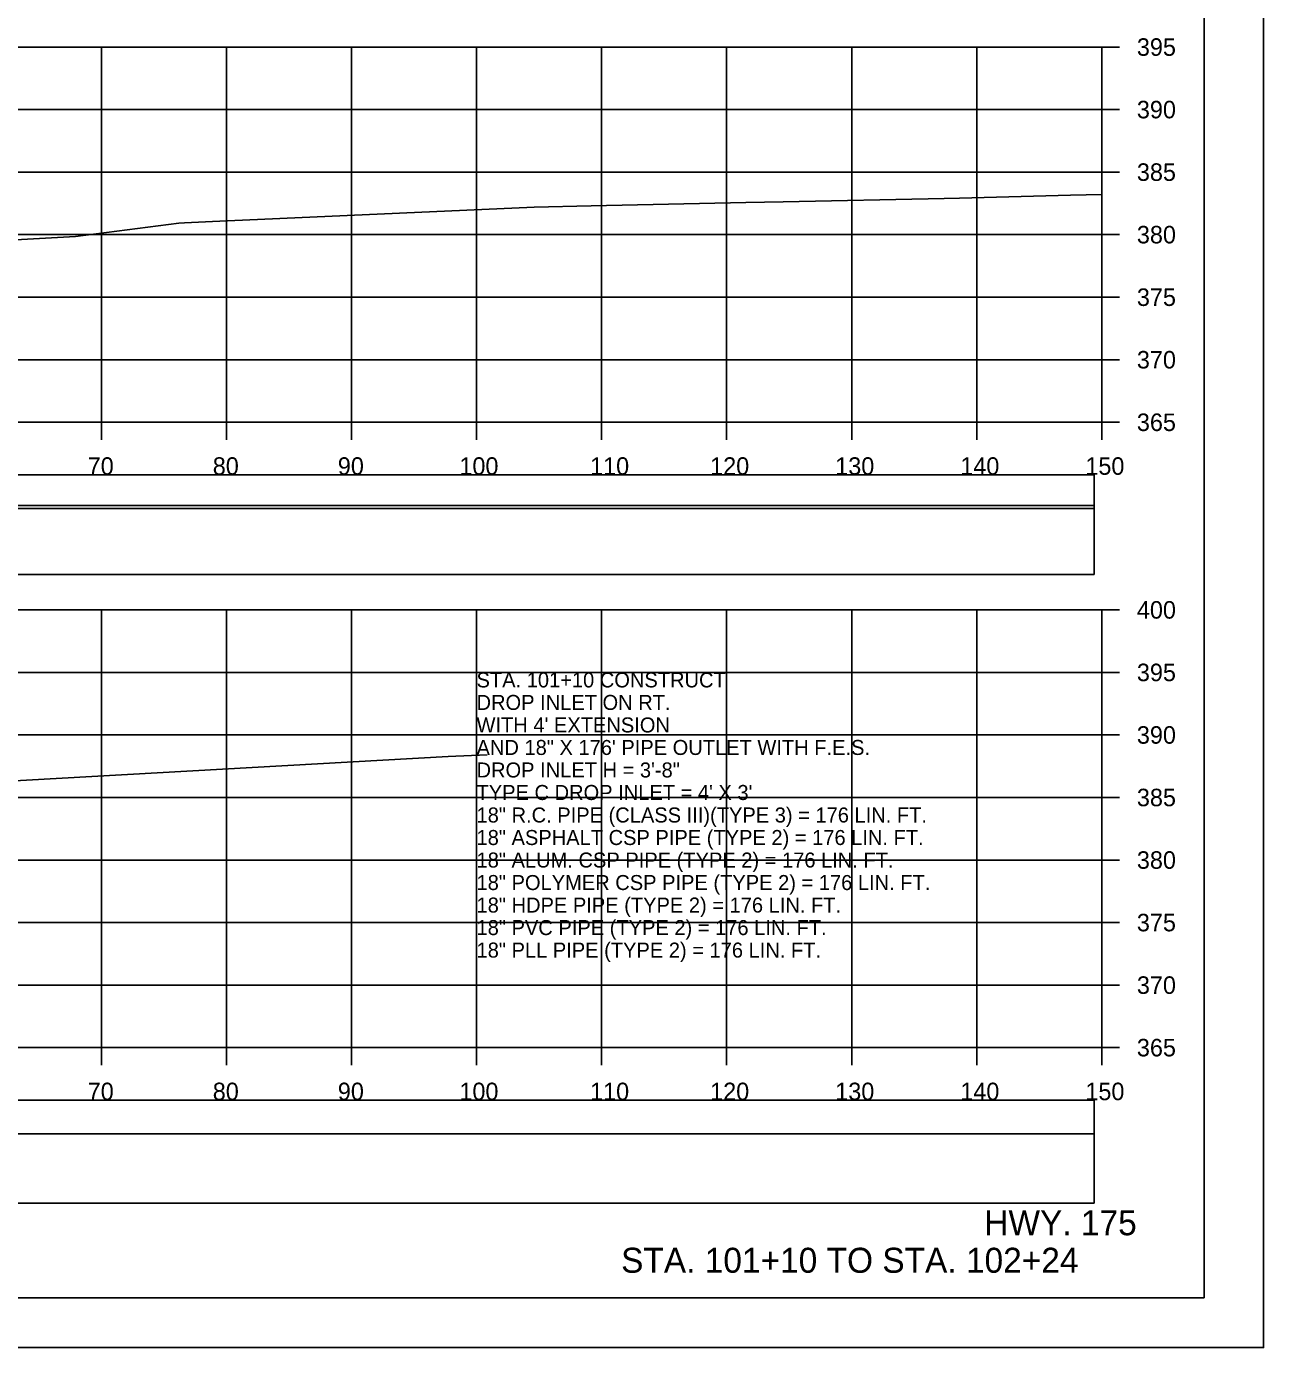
# Model space of a CAD drawing. Extents: x -37291014 to -37290680, y -936053 to -933067.
# Drawn here: x -37290779.1 to -37290680.2, y -935626.6 to -935521 of the extents above; entities that cross this region are included whole.
import ezdxf

# ---------------------------------------------------------------- set-up
doc = ezdxf.new("R2010")
doc.units = 0
for name, color, linetype in [('Default', 7, 'Continuous'), ('R_Axis', 7, 'Continuous'), ('R_Axis Annot', 7, 'Continuous'), ('R_Border', 7, 'Continuous'), ('R_Draft', 7, 'Continuous'), ('R_Exist Surface', 7, 'Continuous'), ('R_Grid', 7, 'Continuous'), ('R_No Plot', 7, 'Continuous'), ('R_Water Annot', 7, 'Continuous')]:
    doc.layers.add(name, color=color, linetype=linetype)

msp = doc.modelspace()

# ---------------------------------------------------------------- linework, layer by layer
at = {"layer": 'Default'}
for points in [[(-37290992.48, -935559.55), (-37290693.72, -935559.55), (-37290693.72, -935556.85), (-37290992.48, -935556.85)], [(-37290992.48, -935564.82), (-37290693.72, -935564.82), (-37290693.72, -935559.3), (-37290992.48, -935559.3)], [(-37290992.48, -935609.55), (-37290693.72, -935609.55), (-37290693.72, -935606.85), (-37290992.48, -935606.85)], [(-37290992.48, -935615.08), (-37290693.72, -935615.08), (-37290693.72, -935609.55), (-37290992.48, -935609.55)]]:
    msp.add_lwpolyline(points, close=True, dxfattribs=at)
at = {"layer": 'R_Axis'}
for p, q in [((-37290693.1, -935552.65), (-37290693.1, -935522.65)), ((-37290691.7, -935522.65), (-37290693.1, -935522.65)), ((-37290691.7, -935527.65), (-37290693.1, -935527.65)), ((-37290691.7, -935532.65), (-37290693.1, -935532.65)), ((-37290691.7, -935537.65), (-37290693.1, -935537.65)), ((-37290691.7, -935542.65), (-37290693.1, -935542.65)), ((-37290691.7, -935547.65), (-37290693.1, -935547.65)), ((-37290993.1, -935552.65), (-37290693.1, -935552.65)), ((-37290773.1, -935554.05), (-37290773.1, -935552.65)), ((-37290763.1, -935554.05), (-37290763.1, -935552.65)), ((-37290753.1, -935554.05), (-37290753.1, -935552.65)), ((-37290743.1, -935554.05), (-37290743.1, -935552.65)), ((-37290733.1, -935554.05), (-37290733.1, -935552.65)), ((-37290723.1, -935554.05), (-37290723.1, -935552.65)), ((-37290713.1, -935554.05), (-37290713.1, -935552.65)), ((-37290703.1, -935554.05), (-37290703.1, -935552.65)), ((-37290693.1, -935554.05), (-37290693.1, -935552.65)), ((-37290691.7, -935552.65), (-37290693.1, -935552.65)), ((-37290693.1, -935602.65), (-37290693.1, -935567.65)), ((-37290691.7, -935567.65), (-37290693.1, -935567.65)), ((-37290691.7, -935572.65), (-37290693.1, -935572.65)), ((-37290691.7, -935577.65), (-37290693.1, -935577.65)), ((-37290691.7, -935582.65), (-37290693.1, -935582.65)), ((-37290691.7, -935587.65), (-37290693.1, -935587.65)), ((-37290691.7, -935592.65), (-37290693.1, -935592.65)), ((-37290691.7, -935597.65), (-37290693.1, -935597.65)), ((-37290993.1, -935602.65), (-37290693.1, -935602.65)), ((-37290773.1, -935604.05), (-37290773.1, -935602.65)), ((-37290763.1, -935604.05), (-37290763.1, -935602.65)), ((-37290753.1, -935604.05), (-37290753.1, -935602.65)), ((-37290743.1, -935604.05), (-37290743.1, -935602.65)), ((-37290733.1, -935604.05), (-37290733.1, -935602.65)), ((-37290723.1, -935604.05), (-37290723.1, -935602.65)), ((-37290713.1, -935604.05), (-37290713.1, -935602.65)), ((-37290703.1, -935604.05), (-37290703.1, -935602.65)), ((-37290693.1, -935604.05), (-37290693.1, -935602.65)), ((-37290691.7, -935602.65), (-37290693.1, -935602.65))]:
    msp.add_line(p, q, dxfattribs=at)
at = {"layer": 'R_Border'}
for q in [(-37290684.92, -935417.19), (-37291001.1, -935622.65)]:
    msp.add_line((-37290684.92, -935622.65), q, dxfattribs=at)
at = {"layer": 'R_Exist Surface'}
for points in [[(-37290789.13, -935538.58), (-37290775.16, -935537.79), (-37290766.9, -935536.73), (-37290766.45, -935536.7), (-37290764.2, -935536.6), (-37290738.48, -935535.46), (-37290733.94, -935535.35), (-37290721.57, -935535.09), (-37290718.57, -935535.02), (-37290705.71, -935534.75), (-37290704.47, -935534.73), (-37290695.62, -935534.49), (-37290693.1, -935534.44)], [(-37290894.59, -935585.8), (-37290871.54, -935585.19), (-37290860.38, -935583.7), (-37290859.66, -935583.61), (-37290856.35, -935583.62), (-37290855.9, -935583.6), (-37290854.08, -935583.4), (-37290853.96, -935583.38), (-37290843.74, -935582.83), (-37290843.16, -935582.81), (-37290842.57, -935582.82), (-37290833.08, -935583.1), (-37290832.57, -935583.12), (-37290832.14, -935583.12), (-37290831.75, -935583.12), (-37290820.5, -935582.55), (-37290818.86, -935582.5), (-37290794.46, -935582.01), (-37290786.13, -935581.66), (-37290779.08, -935581.27), (-37290745.38, -935579.38), (-37290742.25, -935579.24)]]:
    msp.add_lwpolyline(points, dxfattribs=at)
at = {"layer": 'R_Grid'}
for p, q in [((-37290993.1, -935522.65), (-37290693.1, -935522.65)), ((-37290773.1, -935552.65), (-37290773.1, -935522.65)), ((-37290763.1, -935552.65), (-37290763.1, -935522.65)), ((-37290753.1, -935552.65), (-37290753.1, -935522.65)), ((-37290743.1, -935552.65), (-37290743.1, -935522.65)), ((-37290733.1, -935552.65), (-37290733.1, -935522.65)), ((-37290723.1, -935552.65), (-37290723.1, -935522.65)), ((-37290713.1, -935552.65), (-37290713.1, -935522.65)), ((-37290703.1, -935552.65), (-37290703.1, -935522.65)), ((-37290693.1, -935552.65), (-37290693.1, -935522.65)), ((-37290993.1, -935527.65), (-37290693.1, -935527.65)), ((-37290993.1, -935532.65), (-37290693.1, -935532.65)), ((-37290993.1, -935537.65), (-37290693.1, -935537.65)), ((-37290993.1, -935542.65), (-37290693.1, -935542.65)), ((-37290993.1, -935547.65), (-37290693.1, -935547.65)), ((-37290993.1, -935552.65), (-37290693.1, -935552.65)), ((-37290993.1, -935567.65), (-37290693.1, -935567.65)), ((-37290773.1, -935602.65), (-37290773.1, -935567.65)), ((-37290763.1, -935602.65), (-37290763.1, -935567.65)), ((-37290753.1, -935602.65), (-37290753.1, -935567.65)), ((-37290743.1, -935602.65), (-37290743.1, -935567.65)), ((-37290733.1, -935602.65), (-37290733.1, -935567.65)), ((-37290723.1, -935602.65), (-37290723.1, -935567.65)), ((-37290713.1, -935602.65), (-37290713.1, -935567.65)), ((-37290703.1, -935602.65), (-37290703.1, -935567.65)), ((-37290693.1, -935602.65), (-37290693.1, -935567.65)), ((-37290993.1, -935572.65), (-37290693.1, -935572.65)), ((-37290993.1, -935577.65), (-37290693.1, -935577.65)), ((-37290993.1, -935582.65), (-37290693.1, -935582.65)), ((-37290993.1, -935587.65), (-37290693.1, -935587.65)), ((-37290993.1, -935592.65), (-37290693.1, -935592.65)), ((-37290993.1, -935597.65), (-37290693.1, -935597.65)), ((-37290993.1, -935602.65), (-37290693.1, -935602.65))]:
    msp.add_line(p, q, dxfattribs=at)
at = {"layer": 'R_No Plot'}
msp.add_line((-37291013.5, -935626.63), (-37290680.17, -935626.63), dxfattribs=at)
for points in [[(-37291013.51, -935413.29), (-37290680.17, -935413.29), (-37290680.17, -935626.63), (-37291013.51, -935626.63)], [(-37290767.18, -935417.19), (-37290747.56, -935417.19), (-37290747.56, -935427.07), (-37290731.45, -935427.07), (-37290708.25, -935427.07), (-37290708.25, -935451.4), (-37290684.92, -935451.4), (-37290684.92, -935622.65), (-37291001.1, -935622.65), (-37291001.1, -935417.19)]]:
    msp.add_lwpolyline(points, close=True, dxfattribs=at)

# ---------------------------------------------------------------- texts
at = {"layer": 'R_Axis Annot'}
for s, p in [('395', (-37290690.3, -935523.35)), ('390', (-37290690.3, -935528.35)), ('385', (-37290690.3, -935533.35)), ('380', (-37290690.3, -935538.35)), ('375', (-37290690.3, -935543.35)), ('370', (-37290690.3, -935548.35)), ('365', (-37290690.3, -935553.35)), ('70', (-37290774.19, -935556.85)), ('80', (-37290764.19, -935556.85)), ('90', (-37290754.19, -935556.85)), ('100', (-37290744.47, -935556.85)), ('110', (-37290734.02, -935556.85)), ('120', (-37290724.42, -935556.85)), ('130', (-37290714.42, -935556.85)), ('140', (-37290704.42, -935556.85)), ('150', (-37290694.42, -935556.85)), ('400', (-37290690.3, -935568.35)), ('395', (-37290690.3, -935573.35)), ('390', (-37290690.3, -935578.35)), ('385', (-37290690.3, -935583.35)), ('380', (-37290690.3, -935588.35)), ('375', (-37290690.3, -935593.35)), ('370', (-37290690.3, -935598.35)), ('365', (-37290690.3, -935603.35)), ('70', (-37290774.19, -935606.85)), ('80', (-37290764.19, -935606.85)), ('90', (-37290754.19, -935606.85)), ('100', (-37290744.47, -935606.85)), ('110', (-37290734.02, -935606.85)), ('120', (-37290724.42, -935606.85)), ('130', (-37290714.42, -935606.85)), ('140', (-37290704.42, -935606.85)), ('150', (-37290694.42, -935606.85))]:
    msp.add_text(s, height=1.4, dxfattribs=at).set_placement(p)
at = {"layer": 'R_Draft'}
for s, p in [('HWY. 175', (-37290702.5, -935617.65)), ('STA. 101+10 TO STA. 102+24', (-37290731.54, -935620.65))]:
    msp.add_text(s, height=2, dxfattribs=at).set_placement(p)
at = {"layer": 'R_Water Annot'}
for s, p in [('STA. 101+10 CONSTRUCT', (-37290743.1, -935573.85)), ('DROP INLET ON RT.', (-37290743.1, -935575.65)), ("WITH 4' EXTENSION", (-37290743.1, -935577.45)), ('AND 18" X 176\' PIPE OUTLET WITH F.E.S.', (-37290743.1, -935579.25)), ('DROP INLET H = 3\'-8"', (-37290743.1, -935581.05)), ("TYPE C DROP INLET = 4' X 3'", (-37290743.1, -935582.85)), ('18" R.C. PIPE (CLASS III)(TYPE 3) = 176 LIN. FT.', (-37290743.1, -935584.65)), ('18" ASPHALT CSP PIPE (TYPE 2) = 176 LIN. FT.', (-37290743.1, -935586.45)), ('18" ALUM. CSP PIPE (TYPE 2) = 176 LIN. FT.', (-37290743.1, -935588.25)), ('18" POLYMER CSP PIPE (TYPE 2) = 176 LIN. FT.', (-37290743.1, -935590.05)), ('18" HDPE PIPE (TYPE 2) = 176 LIN. FT.', (-37290743.1, -935591.85)), ('18" PVC PIPE (TYPE 2) = 176 LIN. FT.', (-37290743.1, -935593.65)), ('18" PLL PIPE (TYPE 2) = 176 LIN. FT.', (-37290743.1, -935595.45))]:
    msp.add_text(s, height=1.2, dxfattribs=at).set_placement(p)

doc.saveas('drawing.dxf')
